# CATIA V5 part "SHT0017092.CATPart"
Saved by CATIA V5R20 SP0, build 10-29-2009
Part number: SHT0017092-20241021
Source: Unknown
Bounding box of the stored display mesh (mm): x -539.025 to -263.855, y -808.5 to -649.498, z 113.093 to 196.514
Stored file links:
  F:\福田A6\1-数据\6-冻结数据\第九批\设变\滑轨解锁手柄设变20241021\设变后数据\SHT0017092-20241021\SHT0017092.CATPart
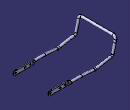
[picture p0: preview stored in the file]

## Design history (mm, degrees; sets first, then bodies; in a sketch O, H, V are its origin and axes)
Body1 "Brep With Voids" (main body)
  Solid1: solid without history
Body2 "Brep With Voids"
  Solid2: solid without history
